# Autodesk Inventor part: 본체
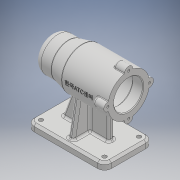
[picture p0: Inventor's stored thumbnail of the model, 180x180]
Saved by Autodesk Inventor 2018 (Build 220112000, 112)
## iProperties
Created: 2019-07
Part Number: 본체
Material: 일반
Document SubType Name: Modeling
Designer: USER
Density: 1 g/cm^3
Appearance: 기본값
Author: USER
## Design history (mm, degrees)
sketch "스케치1"
  geometry: L1 (0, 70)-(112, 70); L2 (112, 70)-(112, 0); L3 (112, 0)-(0, 0); L4 (0, 0)-(0, 70); 1 further point
  constraints: 8 end point, 2 parallel, 1 coincident, 1 horizontal, 1 perpendicular
  dimensions: "d0" = 112 distance of L1.start L1.end; "d1" = 70 distance of L3.end L1.start
extrude "돌출1" new body sketch "스케치1" distance "d2" = 10; taper "d3" = 0 deg
node "작업 평면1"
sketch "스케치2"
  geometry: L1 (0, 80)-(112, 80); L2 (112, 10)-(0, 10) reference; L3 (0, 0)-(112, 0) reference; L4 (0, 80)-(0, 105); L5 (0, 105)-(25, 105); L6 (25, 105)-(45, 110); L7 (45, 110)-(112, 110); L8 (112, 80)-(112, 110); L9 (112, 101)-(97, 101); L10 (97, 101)-(97, 104); L11 (97, 104)-(43, 104); L12 (43, 104)-(43, 101); L13 (43, 101)-(31, 101); L14 (31, 101)-(31, 97.5); L15 (31, 97.5)-(13, 97.5); L16 (13, 97.5)-(13, 96); L17 (13, 96)-(9, 96); L18 (9, 96)-(9, 90.5); L19 (9, 90.5)-(6, 90.5); L20 (6, 90.5)-(6, 80); L21 (0, 80)-(112, 80); 2 further points
  constraints: 38 end point, 11 perpendicular, 5 horizontal, 2 midpoint, 2 point on line, 2 vertical, 1 vertical alignment
  dimensions: "d4" = 112 distance of L1.start L1.end; "d5" = 80 distance between parallel lines of L3 L1; "d6" = 60 diameter of L7 L1; "d7" = 50 diameter of L5 L1; "d8" = 25 distance of L4.end L5.end; "d9" = 45 distance from line of L6.end L4; "d10" = 15 distance of L9.start L9.end; "d11" = 54 distance of L10.end L11.end; "d13" = 18 distance of L14.end L15.end; "d14" = 4 distance of L16.end L17.end; "d15" = 3 distance of L18.end L19.end; "d16" = 42 diameter of L9 L1; "d17" = 48 diameter of L11 L1; "d18" = 42 diameter of L13 L1; "d19" = 12 distance of L12.end L13.end; "d20" = 35 diameter of L15 L1; "d21" = 32 diameter of L17 L1; "d22" = 21 diameter of L19 L1
revolve "회전1" sketch "스케치2" stored, may be unused: angle "d23" = 90 deg
sketch "스케치3"
  geometry: L1 (112, 10)-(0, 10) reference; L2 (20, 10)-(36.025, 54.03); L3 (0, 0)-(0, 10) reference; L4 (87, 10)-(87, 53.035); L5 (112, 0)-(112, 10) reference; L6 (87, 53.035)-(36.025, 54.03); L7 (20, 10)-(87, 10)
  constraints: 8 end point, 2 point on line, 1 horizontal, 1 vertical
  dimensions: "d24" = 20 distance from line of L3 L2.start; "d25" = 110 deg angle of L1 L2; "d26" = 25 distance between parallel lines of L5 L4
extrude "돌출2" join sketch "스케치3" stored distance "d27" = 8; taper "d28" = 0 deg
node "작업 평면2"
sketch "스케치4"
  geometry: L1 (-10, 70)-(-10, 0) reference; L2 (-10, 7)-(-59.395, 15.71); L3 (-10, 63)-(-59.435, 54.283); L4 (0, 0)-(-10, 0) reference; L5 (0, 70)-(-10, 70) reference; L6 (-59.395, 15.71)-(-54.339, 28.739); L7 (-54.339, 28.739)-(-54.339, 46.221); L8 (-54.339, 46.221)-(-59.435, 54.283)
  constraints: 10 end point, 2 point on line, 1 vertical
  dimensions: "d29" = 7 distance from line of L2.start L4; "d30" = 7 distance from line of L3.start L5; "d31" = 100 deg angle of L2 L1; "d32" = 100 deg angle of L1 L3
extrude "돌출3" join sketch "스케치4" stored distance "d33" = 8; taper "d34" = 0 deg
sketch "스케치5"
  geometry: C1 r 6 at (-30, 0); A1 r 30 centre (0, 0) between (29.732, 4) and (29.732, -4) reference; A2 r 30 centre (0, 0) between (29.732, 4) and (29.732, -4) reference; 2 further points
  constraints: 1 centre point, 1 coincident, 1 horizontal alignment, 1 point on circle
  dimensions: "d36" = 12 diameter of C1
extrude "돌출4" join sketch "스케치5" distance "d37" = 16; taper "d38" = 0 deg
sketch "스케치6"
  geometry: C1 r 21 at (30, 0) reference; A1 r 30 centre (30, 0) between (24.03, 29.4) and (0.6, 5.97) reference; A2 r 6 centre (0, 0) between (0.6, 5.97) and (0.6, -5.97) reference; A3 r 30 centre (30, 0) between (0.6, -5.97) and (24.03, -29.4) reference; A4 r 6 centre (30, -30) between (24.03, -29.4) and (35.97, -29.4) reference; A5 r 30 centre (30, 0) between (35.97, -29.4) and (59.4, -5.97) reference; A6 r 6 centre (60, 0) between (59.4, -5.97) and (59.4, 5.97) reference; A7 r 30 centre (30, 0) between (59.4, 5.97) and (35.97, 29.4) reference; A8 r 6 centre (30, 30) between (35.97, 29.4) and (24.03, 29.4) reference; 2 further points
  constraints: 1 coincident
hole "구멍1" sketch "스케치6" at (0, 0) diameter "d42" = 3.242; stored, may be unused: countersink angle "d46" = 90 deg, drill point angle "d48" = 118 deg; dims "d43" = 8, "d44" = 4, "d45" = 2, "d47" = 11
sketch "스케치7"
  geometry: L1 (0, 0)-(0, 70) reference; L2 (0, 70)-(112, 70) reference; L3 (112, 0)-(0, 0) reference; L4 (112, 70)-(112, 0) reference; C1 r 3 at (10, 60); C2 r 3 at (102, 60); C3 r 3 at (102, 10); C4 r 3 at (10, 10)
  constraints: 4 centre point
  dimensions: "d52" = 10 distance from line of C1.centre L1; "d53" = 10 distance from line of C1.centre L2; "d54" = 10 distance from line of L1 C4.centre; "d55" = 10 distance from line of C4.centre L3; "d56" = 10 distance from line of C2.centre L2; "d57" = 10 distance from line of C2.centre L4; "d58" = 10 distance from line of C3.centre L4; "d59" = 10 distance from line of C3.centre L3; "d60" = 6 diameter of C1; "d61" = 6 diameter of C4; "d62" = 6 diameter of C3; "d63" = 6 diameter of C2
extrude "돌출5" cut sketch "스케치7" distance "d64" = 16; taper "d65" = 0 deg
fillet "모깎기1" dims "d66" = 10
fillet "모깎기3" dims "d68" = 10
fillet "모깎기4" dims "d69" = 3
fillet "모깎기5" dims "d70" = 3
fillet "모깎기6" dims "d71" = 3
fillet "모깎기7" dims "d72" = 1
chamfer "모따기1" distance "d73" = 3; stored, may be unused: second distance "d74" = 2, angle "d75" = 45 deg
fillet "모깎기8" dims "d76" = 3
fillet "모깎기9" dims "d77" = 0.3
fillet "모깎기10" dims "d78" = 3
fillet "모깎기11" dims "d79" = 3
chamfer "모따기2" distance "d80" = 1; stored, may be unused: second distance "d81" = 2, angle "d82" = 45 deg
node "작업 평면4"
sketch "스케치9"
  geometry: L1 (33.5, 5.998)-(33.5, -5.998) reference; L2 (33.5, 36)-(33.5, 30.171) reference; 3 further points
  constraints: 1 horizontal alignment, 1 midpoint, 1 other
  dimensions: "d83" = 42 distance from line of L2 point (-8.5, 0)
feature "엠보싱1" sketch "스케치9" dims "d0" = 112, "d1" = 70, "d84" = 0.5, "d85" = 0
node "솔리드1"
pattern_circular "원형 패턴1" dims angle "d40" = 360 deg
pattern_circular "원형 패턴2" dims angle "d50" = 360 deg
node "투영된 루프1"
